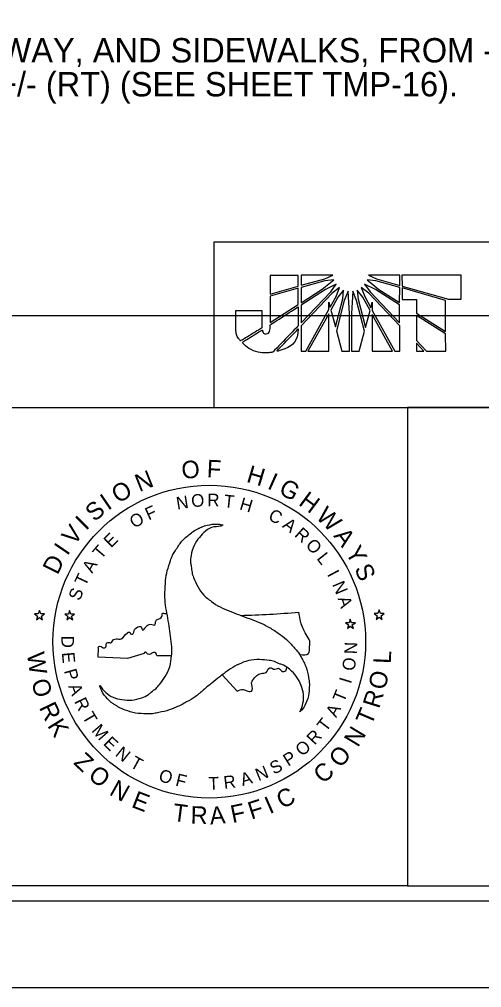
# Model space of a CAD drawing. Extents: x 764226 to 769781, y 650021 to 652521.
# Drawn here: x 767759.5 to 767892.6, y 651421.3 to 651699.7 of the extents above; entities that cross this region are included whole.
import ezdxf

# ---------------------------------------------------------------- set-up
doc = ezdxf.new("R2010")
doc.units = 0
for name, color, linetype in [('Default', 7, 'Continuous'), ('DEV BORDER CELL', 7, 'Continuous'), ('DEV DOT SWIRL SEAL CELL', 7, 'Continuous'), ('Scratch_Level_0', 7, 'Continuous'), ('Sheet Plan CELL', 7, 'Continuous'), ('Sheet Plot Border Outside CELL', 7, 'Continuous'), ('Text', 7, 'Continuous')]:
    doc.layers.add(name, color=color, linetype=linetype)

msp = doc.modelspace()

# ---------------------------------------------------------------- linework, layer by layer
at = {"layer": 'Default'}
for p, q in [((767839.76, 651626.07), (767831.66, 651626.07)), ((767831.66, 651626.07), (767831.67, 651620.69)), ((767839.76, 651622.95), (767839.76, 651626.07)), ((767849.71, 651626.12), (767840.6, 651626.11)), ((767840.6, 651626.11), (767840.6, 651623.21)), ((767840.6, 651623.21), (767847.39, 651625.09)), ((767847.39, 651624.46), (767840.61, 651622.59)), ((767846.68, 651622.06), (767850.04, 651624.79)), ((767847.39, 651625.09), (767849.71, 651626.12)), ((767850.04, 651624.79), (767847.39, 651624.46)), ((767859.58, 651624.79), (767862.97, 651622.02)), ((767862.07, 651624.48), (767859.58, 651624.79)), ((767869.01, 651626.1), (767860.03, 651626.13)), ((767860.03, 651626.13), (767862.3, 651625.06)), ((767869.01, 651622.57), (767862.07, 651624.48)), ((767862.3, 651625.06), (767869.01, 651623.19)), ((767869.01, 651623.19), (767869.01, 651626.1)), ((767886.65, 651626.15), (767869.63, 651626.14)), ((767869.63, 651626.14), (767869.64, 651623.01)), ((767886.66, 651619.18), (767886.65, 651626.15)), ((767831.67, 651620.69), (767839.76, 651622.95)), ((767839.76, 651622.36), (767831.67, 651620.08)), ((767839.77, 651617.67), (767839.76, 651622.36)), ((767840.61, 651622.59), (767840.61, 651618.2)), ((767840.61, 651618.2), (767846.68, 651622.06)), ((767847.62, 651621.96), (767840.61, 651617.5)), ((767840.61, 651612.45), (767849.14, 651621.34)), ((767849.49, 651620.9), (767840.62, 651611.59)), ((767850.7, 651623.53), (767847.62, 651621.96)), ((767849.14, 651621.34), (767850.7, 651623.53)), ((767851.64, 651622.56), (767849.49, 651620.9)), ((767850.65, 651619.96), (767851.64, 651622.56)), ((767852.8, 651621.84), (767851.2, 651619.78)), ((767852.58, 651619.34), (767852.8, 651621.84)), ((767854.14, 651621.48), (767853.03, 651618.88)), ((767854.49, 651615.09), (767854.14, 651621.48)), ((767855.48, 651621.48), (767855.07, 651615.09)), ((767856.55, 651618.89), (767855.48, 651621.48)), ((767856.77, 651621.84), (767857.04, 651619.25)), ((767858.34, 651619.78), (767856.77, 651621.84)), ((767857.92, 651622.56), (767858.91, 651619.97)), ((767860.07, 651620.91), (767857.92, 651622.56)), ((767858.87, 651623.54), (767860.43, 651621.31)), ((767862, 651621.98), (767858.87, 651623.54)), ((767868.97, 651611.54), (767860.07, 651620.91)), ((767860.43, 651621.31), (767868.96, 651612.38)), ((767868.96, 651617.56), (767862, 651621.98)), ((767862.97, 651622.02), (767868.96, 651618.28)), ((767868.96, 651618.28), (767869.01, 651622.57)), ((767869.64, 651623.01), (767869.64, 651622.92)), ((767869.64, 651622.92), (767883.04, 651619.18)), ((767869.64, 651622.44), (767869.64, 651622.39)), ((767882.19, 651618.87), (767869.64, 651622.44)), ((767869.64, 651622.39), (767869.64, 651619.13)), ((767831.67, 651620.08), (767831.68, 651612.53)), ((767848.56, 651616.21), (767848.56, 651618.35)), ((767848.56, 651618.35), (767848.96, 651616.88)), ((767848.96, 651616.88), (767850.65, 651619.96)), ((767851.2, 651619.78), (767849.19, 651616.11)), ((767850.49, 651611.25), (767852.58, 651619.34)), ((767853.03, 651618.88), (767850.76, 651610.13)), ((767858.88, 651610), (767856.55, 651618.89)), ((767857.04, 651619.25), (767859.15, 651611.07)), ((767860.44, 651615.99), (767858.34, 651619.78)), ((767858.91, 651619.97), (767860.65, 651616.75)), ((767860.65, 651616.75), (767861.06, 651618.36)), ((767861.06, 651618.36), (767861.07, 651615.99)), ((767869.64, 651619.13), (767873.8, 651619.13)), ((767873.8, 651619.13), (767873.8, 651615.24)), ((767882.19, 651609.93), (767882.19, 651618.87)), ((767883.04, 651619.18), (767886.66, 651619.18)), ((767831.68, 651612.53), (767839.77, 651617.67)), ((767840.61, 651617.5), (767840.61, 651612.45)), ((767841.96, 651604.24), (767848.56, 651616.21)), ((767849.19, 651616.11), (767850.49, 651611.25)), ((767859.15, 651611.07), (767860.44, 651615.99)), ((767861.07, 651615.99), (767867.54, 651604.27)), ((767868.96, 651612.38), (767868.96, 651617.56)), ((767873.8, 651615.24), (767882.19, 651609.93)), ((767848.56, 651615.05), (767842.59, 651604.24)), ((767848.62, 651604.25), (767848.56, 651615.05)), ((767854.5, 651604.3), (767854.49, 651615.09)), ((767855.07, 651615.09), (767855.08, 651604.3)), ((767866.87, 651604.31), (767861.07, 651614.83)), ((767861.07, 651614.83), (767861.08, 651604.3)), ((767873.8, 651614.57), (767873.81, 651607.33)), ((767882.19, 651609.3), (767873.8, 651614.57)), ((767840.62, 651611.59), (767840.62, 651604.24)), ((767850.76, 651610.13), (767852.29, 651604.29)), ((767857.32, 651604.3), (767858.88, 651610)), ((767868.97, 651604.27), (767868.97, 651611.54)), ((767873.81, 651607.33), (767876.71, 651604.28)), ((767882.2, 651604.28), (767882.19, 651609.3)), ((767840.62, 651604.24), (767841.96, 651604.24)), ((767842.59, 651604.24), (767848.62, 651604.25)), ((767852.29, 651604.29), (767854.5, 651604.3)), ((767855.08, 651604.3), (767857.32, 651604.3)), ((767861.08, 651604.3), (767866.87, 651604.31)), ((767867.54, 651604.27), (767868.97, 651604.27)), ((767875.91, 651604.27), (767873.81, 651606.54)), ((767873.81, 651606.54), (767873.81, 651604.27)), ((767873.81, 651604.27), (767875.91, 651604.27)), ((767876.71, 651604.28), (767882.2, 651604.28))]:
    msp.add_line(p, q, dxfattribs=at)
for points in [[(767831.67, 651620.69), (767839.76, 651622.95), (767839.76, 651626.07), (767831.66, 651626.07), (767831.67, 651620.69)], [(767847.39, 651625.09), (767849.71, 651626.12), (767840.6, 651626.11), (767840.6, 651623.21), (767847.39, 651625.09)], [(767840.61, 651622.59), (767840.61, 651618.2), (767846.68, 651622.06), (767850.04, 651624.79), (767847.39, 651624.46), (767840.61, 651622.59)], [(767859.58, 651624.79), (767862.97, 651622.02), (767868.96, 651618.28), (767869.01, 651622.57), (767862.07, 651624.48), (767859.58, 651624.79)], [(767862.3, 651625.06), (767869.01, 651623.19), (767869.01, 651626.1), (767860.03, 651626.13), (767862.3, 651625.06)], [(767831.68, 651612.53), (767839.77, 651617.67), (767839.76, 651622.36), (767831.67, 651620.08), (767831.68, 651612.53)], [(767840.61, 651617.5), (767840.61, 651612.45), (767849.14, 651621.34), (767850.7, 651623.53), (767847.62, 651621.96), (767840.61, 651617.5)], [(767851.64, 651622.56), (767849.49, 651620.9), (767840.62, 651611.59), (767840.62, 651604.24), (767841.96, 651604.24), (767848.56, 651616.21), (767848.56, 651618.35), (767848.96, 651616.88), (767850.65, 651619.96), (767851.64, 651622.56)], [(767852.8, 651621.84), (767851.2, 651619.78), (767849.19, 651616.11), (767850.49, 651611.25), (767852.58, 651619.34), (767852.8, 651621.84)], [(767853.03, 651618.88), (767850.76, 651610.13), (767852.29, 651604.29), (767854.5, 651604.3), (767854.49, 651615.09), (767854.14, 651621.48), (767853.03, 651618.88)], [(767855.48, 651621.48), (767855.07, 651615.09), (767855.08, 651604.3), (767857.32, 651604.3), (767858.88, 651610), (767856.55, 651618.89), (767855.48, 651621.48)], [(767856.77, 651621.84), (767857.04, 651619.25), (767859.15, 651611.07), (767860.44, 651615.99), (767858.34, 651619.78), (767856.77, 651621.84)], [(767857.92, 651622.56), (767858.91, 651619.97), (767860.65, 651616.75), (767861.06, 651618.36), (767861.07, 651615.99), (767867.54, 651604.27), (767868.97, 651604.27), (767868.97, 651611.54), (767860.07, 651620.91), (767857.92, 651622.56)], [(767858.87, 651623.54), (767860.43, 651621.31), (767868.96, 651612.38), (767868.96, 651617.56), (767862, 651621.98), (767858.87, 651623.54)], [(767869.64, 651622.44), (767869.64, 651622.39), (767869.64, 651619.13), (767873.8, 651619.13), (767873.8, 651615.24), (767882.19, 651609.93), (767882.19, 651618.87), (767869.64, 651622.44)], [(767842.59, 651604.24), (767848.62, 651604.25), (767848.56, 651615.05), (767842.59, 651604.24)], [(767861.08, 651604.3), (767866.87, 651604.31), (767861.07, 651614.83), (767861.08, 651604.3)], [(767873.8, 651614.57), (767873.81, 651607.33), (767876.71, 651604.28), (767882.2, 651604.28), (767882.19, 651609.3), (767873.8, 651614.57), (767873.8, 651614.57)], [(767873.81, 651604.27), (767873.81, 651604.27), (767875.91, 651604.27), (767873.81, 651606.54), (767873.81, 651604.27)]]:
    msp.add_lwpolyline(points, dxfattribs=at)
for points in [[(767829.35, 651616), (767829.35, 651616), (767821.85, 651616), (767821.85, 651616), (767821.85, 651616), (767821.86, 651611.31), (767821.86, 651611.31), (767821.86, 651611.31), (767821.86, 651610.81), (767821.86, 651610.81), (767821.86, 651609.34), (767822.34, 651608.18), (767823.2, 651607.21), (767823.2, 651607.21), (767829.35, 651610.95), (767829.35, 651611.05), (767829.35, 651611.05), (767829.35, 651616), (767829.35, 651616)], [(767829.35, 651616), (767829.35, 651616), (767821.85, 651616), (767821.85, 651616), (767821.85, 651616), (767821.86, 651611.31), (767821.86, 651611.31), (767821.86, 651611.31), (767821.86, 651610.81), (767821.86, 651610.81), (767821.86, 651609.34), (767822.34, 651608.18), (767823.2, 651607.21), (767823.2, 651607.21), (767829.35, 651610.95), (767829.35, 651611.05), (767829.35, 651611.05), (767829.35, 651616), (767829.35, 651616)], [(767830.52, 651609.26), (767830.04, 651609.26), (767829.62, 651609.52), (767829.45, 651610.42), (767829.45, 651610.42), (767823.64, 651606.82), (767823.64, 651606.82), (767825.43, 651604.94), (767828.29, 651603.82), (767830.71, 651603.82), (767831.34, 651603.82), (767831.82, 651603.87), (767832.49, 651604.01), (767832.49, 651604.01), (767839.77, 651611.55), (767839.77, 651611.55), (767839.77, 651611.55), (767839.77, 651617), (767839.77, 651617), (767839.77, 651617), (767831.68, 651611.85), (767831.68, 651611.85), (767831.68, 651609.81), (767831.18, 651609.26), (767830.52, 651609.26)], [(767830.52, 651609.26), (767830.04, 651609.26), (767829.62, 651609.52), (767829.45, 651610.42), (767829.45, 651610.42), (767823.64, 651606.82), (767823.64, 651606.82), (767825.43, 651604.94), (767828.29, 651603.82), (767830.71, 651603.82), (767831.34, 651603.82), (767831.82, 651603.87), (767832.49, 651604.01), (767832.49, 651604.01), (767839.77, 651611.55), (767839.77, 651611.55), (767839.77, 651611.55), (767839.77, 651617), (767839.77, 651617), (767839.77, 651617), (767831.68, 651611.85), (767831.68, 651611.85), (767831.68, 651609.81), (767831.18, 651609.26), (767830.52, 651609.26)], [(767839.77, 651610.7), (767839.77, 651610.7), (767833.47, 651604.18), (767833.47, 651604.18), (767836.56, 651604.95), (767839.63, 651606.99), (767839.77, 651610.7)], [(767839.77, 651610.7), (767839.77, 651610.7), (767833.47, 651604.18), (767833.47, 651604.18), (767836.56, 651604.95), (767839.63, 651606.99), (767839.77, 651610.7)]]:
    msp.add_open_spline(points, degree=3, dxfattribs=at)
at = {"layer": 'DEV BORDER CELL'}
for points in [[(768112.34, 652496.28), (766612.34, 652496.28), (766612.34, 651446.28), (768112.34, 651446.28)], [(767757.19, 651588.05), (767871.19, 651588.05), (767871.19, 651450.55), (767757.19, 651450.55)], [(768107.19, 651588.05), (767871.19, 651588.05), (767871.19, 651450.55), (768107.19, 651450.55)]]:
    msp.add_lwpolyline(points, close=True, dxfattribs=at)
at = {"layer": 'DEV DOT SWIRL SEAL CELL'}
for p, q in [((767765.32, 651529.72), (767765, 651528.71)), ((767765.68, 651528.71), (767765.32, 651529.72)), ((767774, 651529.7), (767773.68, 651528.7)), ((767774.36, 651528.7), (767774, 651529.7)), ((767863.05, 651529.86), (767862.73, 651528.85)), ((767863.41, 651528.85), (767863.05, 651529.86)), ((767763.92, 651528.71), (767764.8, 651528.07)), ((767765, 651528.71), (767763.92, 651528.71)), ((767764.8, 651528.07), (767764.48, 651527.03)), ((767764.48, 651527.03), (767765.32, 651527.67)), ((767765.32, 651527.67), (767766.21, 651527.03)), ((767765.32, 651527.67), (767766.21, 651527.03)), ((767766.77, 651528.71), (767765.68, 651528.71)), ((767765.89, 651528.07), (767766.77, 651528.71)), ((767765.89, 651528.07), (767766.77, 651528.71)), ((767766.21, 651527.03), (767765.89, 651528.07)), ((767766.21, 651527.03), (767765.89, 651528.07)), ((767773.68, 651528.7), (767772.6, 651528.7)), ((767772.6, 651528.7), (767773.48, 651528.06)), ((767773.48, 651528.06), (767773.16, 651527.01)), ((767773.16, 651527.01), (767774, 651527.66)), ((767774, 651527.66), (767774.89, 651527.01)), ((767775.45, 651528.7), (767774.36, 651528.7)), ((767774.56, 651528.06), (767775.45, 651528.7)), ((767774.89, 651527.01), (767774.56, 651528.06)), ((767854.45, 651526.21), (767853.37, 651526.21)), ((767853.37, 651526.21), (767854.25, 651525.57)), ((767854.77, 651527.21), (767854.45, 651526.21)), ((767855.13, 651526.21), (767854.77, 651527.21)), ((767856.22, 651526.21), (767855.13, 651526.21)), ((767855.33, 651525.57), (767856.22, 651526.21)), ((767862.73, 651528.85), (767861.64, 651528.85)), ((767861.64, 651528.85), (767862.53, 651528.21)), ((767862.53, 651528.21), (767862.2, 651527.17)), ((767862.2, 651527.17), (767863.05, 651527.81)), ((767863.05, 651527.81), (767863.93, 651527.17)), ((767864.49, 651528.85), (767863.41, 651528.85)), ((767863.61, 651528.21), (767864.49, 651528.85)), ((767863.93, 651527.17), (767863.61, 651528.21)), ((767854.25, 651525.57), (767853.93, 651524.53)), ((767853.93, 651524.53), (767854.77, 651525.17)), ((767854.77, 651525.17), (767855.65, 651524.53)), ((767855.65, 651524.53), (767855.33, 651525.57)), ((767782.25, 651516.27), (767782.33, 651518.92)), ((767790.64, 651515.96), (767782.25, 651516.27)), ((767795.44, 651517.37), (767790.64, 651515.96)), ((767799.14, 651516.81), (767803.36, 651516.77)), ((767817.89, 651511.19), (767822.2, 651506.52))]:
    msp.add_line(p, q, dxfattribs=at)
for start, end in [(265.6785, 265.9762), (271.2035, 275.3236)]:
    msp.add_arc((767818.28, 651761.45), 233.19, start, end, dxfattribs=at)
for points in [[(767782.66, 651508.16), (767784.4, 651506.14), (767786.58, 651504.75), (767789.07, 651504.1), (767791.89, 651503.94), (767794.76, 651504.61), (767796.67, 651505.58), (767797.47, 651506.22), (767798.87, 651507.33), (767799.86, 651508.4), (767801.53, 651510.76), (767802.82, 651513.55), (767803.35, 651516.75), (767803.38, 651517.02), (767803.35, 651520.02), (767802.95, 651523.06), (767802.52, 651525.98), (767801.98, 651529.01), (767801.5, 651532.02), (767801.45, 651534.95), (767801.64, 651538.3), (767802.12, 651541.18), (767803.06, 651544.13), (767803.57, 651545.53), (767804.27, 651546.65), (767806.01, 651549.31), (767808.29, 651551.45), (767809.8, 651552.59), (767811.22, 651553.34), (767811.46, 651553.47), (767814.31, 651554.38), (767817.1, 651554.49), (767818.04, 651554.25)], [(767818.12, 651554.33), (767818.04, 651554.25), (767815.46, 651553.77), (767813.13, 651552.56), (767811.33, 651550.73), (767809.8, 651548.4), (767808.94, 651545.55), (767808.8, 651543.43), (767808.99, 651542.41), (767809.23, 651540.64), (767809.64, 651539.24), (767810.9, 651536.64), (767812.64, 651534.12), (767815.17, 651532.05), (767815.38, 651531.89), (767817.96, 651530.41), (767820.83, 651529.23), (767823.57, 651528.16), (767826.44, 651527.11), (767829.28, 651525.98), (767831.86, 651524.59), (767834.68, 651522.76), (767836.91, 651520.91), (767839, 651518.63), (767839.97, 651517.47), (767840.59, 651516.29), (767842.04, 651513.47), (767842.73, 651510.41), (767842.98, 651508.53), (767842.92, 651506.92), (767842.92, 651506.65), (767842.25, 651503.73), (767840.94, 651501.26), (767840.29, 651500.59)], [(767782.33, 651518.92), (767782.25, 651519.18), (767782.7, 651519.46), (767783.94, 651518.95), (767784.56, 651519.49), (767784.53, 651520.03), (767785.04, 651520.56), (767785.89, 651520.39), (767786.65, 651521.36), (767787.36, 651521.55), (767788.86, 651521.55), (767790.64, 651523.33), (767791.37, 651523.45), (767791.57, 651522.96), (767792.02, 651522.88), (767792.81, 651524.35), (767793.01, 651524.55), (767794.37, 651525.11), (767794.73, 651524.83), (767794.85, 651524.18), (767795.04, 651524.07), (767795.5, 651524.38), (767796.12, 651525.17), (767797.25, 651525.76), (767798.55, 651525.59), (767798.77, 651526.67), (767800.3, 651527.68), (767800.61, 651528.31), (767800.7, 651528.93)], [(767840.22, 651517.04), (767842.69, 651517.34), (767843.05, 651519.29), (767843.08, 651520.93), (767842.06, 651522.83), (767840.54, 651526.3), (767839.92, 651529.27)], [(767799.14, 651516.81), (767798.8, 651517.46), (767798.13, 651517.65), (767797.19, 651517.17), (767796.51, 651517.2), (767795.75, 651517.77), (767795.44, 651517.37)], [(767840.29, 651500.59), (767841.15, 651503.06), (767841.29, 651505.66), (767840.59, 651508.16), (767839.33, 651510.65), (767837.31, 651512.8), (767835.54, 651513.98), (767834.55, 651514.33), (767832.94, 651515.03), (767831.46, 651515.35), (767828.61, 651515.59), (767825.53, 651515.32), (767822.49, 651514.17), (767822.25, 651514.06), (767819.68, 651512.53), (767817.23, 651510.68), (767814.9, 651508.86), (767812.56, 651506.87), (767810.17, 651504.94), (767807.68, 651503.43), (767804.67, 651501.9), (767801.96, 651500.91), (767798.95, 651500.24), (767797.45, 651499.97), (767796.13, 651500.02), (767792.99, 651500.19), (767789.96, 651501.1), (767788.24, 651501.82), (767786.87, 651502.71), (767786.63, 651502.84), (767784.43, 651504.86), (767782.95, 651507.22), (767782.66, 651508.16)], [(767822.2, 651506.52), (767823.9, 651507.03), (767825.31, 651506.49), (767825.99, 651506.38), (767826.55, 651506.8), (767826.38, 651508.92), (767826.86, 651509.91), (767829.15, 651511.61), (767830.57, 651511.92), (767831.61, 651513.22), (767832.03, 651513.19), (767832.68, 651512.82), (767834.13, 651513.11), (767835.28, 651512.17), (767835.96, 651512.23), (767836.5, 651513.29)]]:
    msp.add_spline(points, degree=3, dxfattribs=at)
at = {"layer": 'Scratch_Level_0'}
msp.add_lwpolyline([(768062.34, 652446.28), (766662.34, 652446.28), (766662.34, 651496.28), (767541.19, 651496.28), (767541.19, 651614.55), (768062.34, 651614.55)], close=True, dxfattribs=at)
at = {"layer": 'Sheet Plan CELL'}
msp.add_lwpolyline([(768107.19, 651635.57), (767815.52, 651635.57), (767815.52, 651588.05), (768107.19, 651588.05)], close=True, dxfattribs=at)
at = {"layer": 'Sheet Plot Border Outside CELL'}
msp.add_lwpolyline([(766449.34, 651421.28), (768137.34, 651421.28), (768137.34, 652521.28), (766449.34, 652521.28)], close=True, dxfattribs=at)
at = {"layer": 'Text'}
msp.add_circle((767814.19, 651520.76), 44.97, dxfattribs=at)

# ---------------------------------------------------------------- texts
at = {"layer": 'Default'}
for s, p in [('PROPOSED ROADWAY, AND SIDEWALKS, FROM -L- STA. 50+98 +/- ', (767671.45, 651687.29)), ('TO -L- STA. 60+50 +/- (RT) (SEE SHEET TMP-16).', (767671.45, 651677.53))]:
    msp.add_text(s, height=7, rotation=359.9999, dxfattribs=at).set_placement(p)
at = {"layer": 'DEV DOT SWIRL SEAL CELL'}
for s, height, rotation, p in [('O', 5.04, 5.7649, (767806.45, 651567.49)), ('F', 5.04, 357.2575, (767813.4, 651568.04)), ('H', 5.04, 343.454, (767824.63, 651566.75)), ('N', 5.04, 21.5861, (767794.05, 651563.75)), ('I', 5.04, 335.804, (767830.63, 651564.88)), ('O', 5.04, 30.0935, (767787.94, 651560.38)), ('G', 5.04, 331.5167, (767833.86, 651563.49)), ('I', 5.04, 34.3808, (767785.06, 651558.35)), ('N', 3.63, 9.0227, (767804.97, 651558.7)), ('O', 3.63, 3.9446, (767809.11, 651559.42)), ('R', 3.63, 358.8665, (767813.59, 651559.69)), ('H', 5.04, 323.4632, (767839.61, 651560.24)), ('S', 5.04, 40.5848, (767781.2, 651555.04)), ('F', 3.63, 24.2569, (767796.75, 651555.58)), ('H', 3.63, 343.6322, (767822.67, 651558.83)), ('W', 5.04, 315.8133, (767844.61, 651556.44)), ('I', 5.04, 44.8722, (767778.74, 651552.51)), ('O', 3.63, 29.335, (767792.54, 651553.23)), ('C', 3.63, 333.4761, (767830.9, 651555.91)), ('V', 5.04, 51.5806, (767775.3, 651548.22)), ('A', 3.63, 323.3199, (767835, 651553.79)), ('E', 3.63, 44.5692, (767785.93, 651547.55)), ('R', 3.63, 318.2418, (767838.49, 651551.23)), ('A', 5.04, 306.7762, (767849.79, 651551.14)), ('I', 5.04, 55.8679, (767773.37, 651545.27)), ('T', 3.63, 49.6473, (767783.07, 651544.24)), ('O', 3.63, 313.1637, (767841.7, 651548.32)), ('Y', 5.04, 299.7484, (767853.21, 651546.49)), ('L', 3.63, 308.0856, (767844.92, 651544.64)), ('D', 5.04, 63.459, (767770.52, 651539.74)), ('A', 3.63, 59.8035, (767780.51, 651540.25)), ('S', 5.04, 293.2249, (767855.85, 651541.84)), ('T', 3.63, 64.8816, (767778.57, 651536.46)), ('I', 3.63, 297.9295, (767847.96, 651540.14)), ('N', 3.63, 292.8514, (767849.48, 651537.23)), ('S', 3.63, 69.9597, (767776.98, 651532.32)), ('A', 3.63, 287.7733, (767851.08, 651533.18)), ('D', 3.63, 270.272, (767771.64, 651522.46)), ('N', 3.63, 87.733, (767856.63, 651517.1)), ('E', 3.63, 275.3501, (767771.75, 651517.6)), ('O', 3.63, 82.9269, (767856, 651512.23)), ('P', 3.63, 285.5063, (767772.36, 651512.39)), ('I', 3.63, 72.7707, (767854.92, 651508.47)), ('A', 3.63, 290.5843, (767773.56, 651507.93)), ('T', 3.63, 67.6926, (767852.93, 651503.08)), ('R', 3.63, 295.6624, (767775.23, 651503.6)), ('A', 3.63, 62.6145, (767850.7, 651498.74)), ('T', 3.63, 300.7405, (767777.51, 651499.19)), ('T', 3.63, 52.4584, (767847.75, 651494.6)), ('M', 3.63, 310.8967, (767780.13, 651495.1)), ('E', 3.63, 315.9748, (767783.47, 651491.28)), ('R', 3.63, 47.3803, (767844.49, 651490.85)), ('N', 3.63, 321.0529, (767786.89, 651488.12)), ('O', 3.63, 42.3022, (767840.96, 651487.59)), ('T', 3.63, 331.209, (767791.13, 651484.88)), ('P', 3.63, 32.146, (767836.89, 651484.77)), ('N', 3.63, 21.9899, (767828.35, 651480.59)), ('S', 3.63, 27.068, (767832.76, 651482.46)), ('O', 3.63, 341.3652, (767799.34, 651480.86)), ('F', 3.63, 346.4433, (767804.26, 651479.38)), ('T', 3.63, 1.6775, (767814.02, 651478.19)), ('R', 3.63, 6.7556, (767818.51, 651478.43)), ('A', 3.63, 16.9118, (767823.77, 651479.2))]:
    msp.add_text(s, height=height, rotation=rotation, dxfattribs=at).set_placement(p)
at = {"layer": 'Text'}
for s, height, rotation, p in [('T', 3.63, 353.7884, (767818.22, 651559.47)), ('W', 5.04, 278.15, (767761.71, 651517.38)), ('L', 5.04, 87.429, (767866.39, 651514.31)), ('O', 5.04, 287.1147, (767762.87, 651509.25)), ('O', 5.04, 78.9896, (767864.88, 651506.72)), ('R', 5.04, 72.7519, (767863.05, 651501.29)), ('R', 5.04, 295.5541, (767765.12, 651501.84)), ('T', 5.04, 66.881, (767860.8, 651496.4)), ('K', 5.04, 301.7918, (767767.46, 651496.62)), ('N', 5.04, 58.892, (767856.97, 651490.15)), ('O', 5.04, 50.4526, (767852.01, 651484.21)), ('Z', 5.04, 316.1688, (767774.92, 651485.77)), ('O', 5.04, 322.5233, (767779.03, 651481.64)), ('C', 5.04, 43.0807, (767847.01, 651479.66)), ('N', 5.04, 330.9626, (767785.15, 651476.9)), ('E', 5.04, 338.9517, (767791.53, 651473.29)), ('I', 5.04, 23.7503, (767831.55, 651471.11)), ('C', 5.04, 28.0033, (767835.19, 651472.53)), ('T', 5.04, 352.6948, (767803.46, 651469.27)), ('R', 5.04, 358.5656, (767808.78, 651468.44)), ('A', 5.04, 4.8034, (767814.49, 651468.16)), ('F', 5.04, 11.7751, (767820.88, 651468.59)), ('F', 5.04, 17.7627, (767826.28, 651469.57))]:
    msp.add_text(s, height=height, rotation=rotation, dxfattribs=at).set_placement(p)

doc.saveas('drawing.dxf')
